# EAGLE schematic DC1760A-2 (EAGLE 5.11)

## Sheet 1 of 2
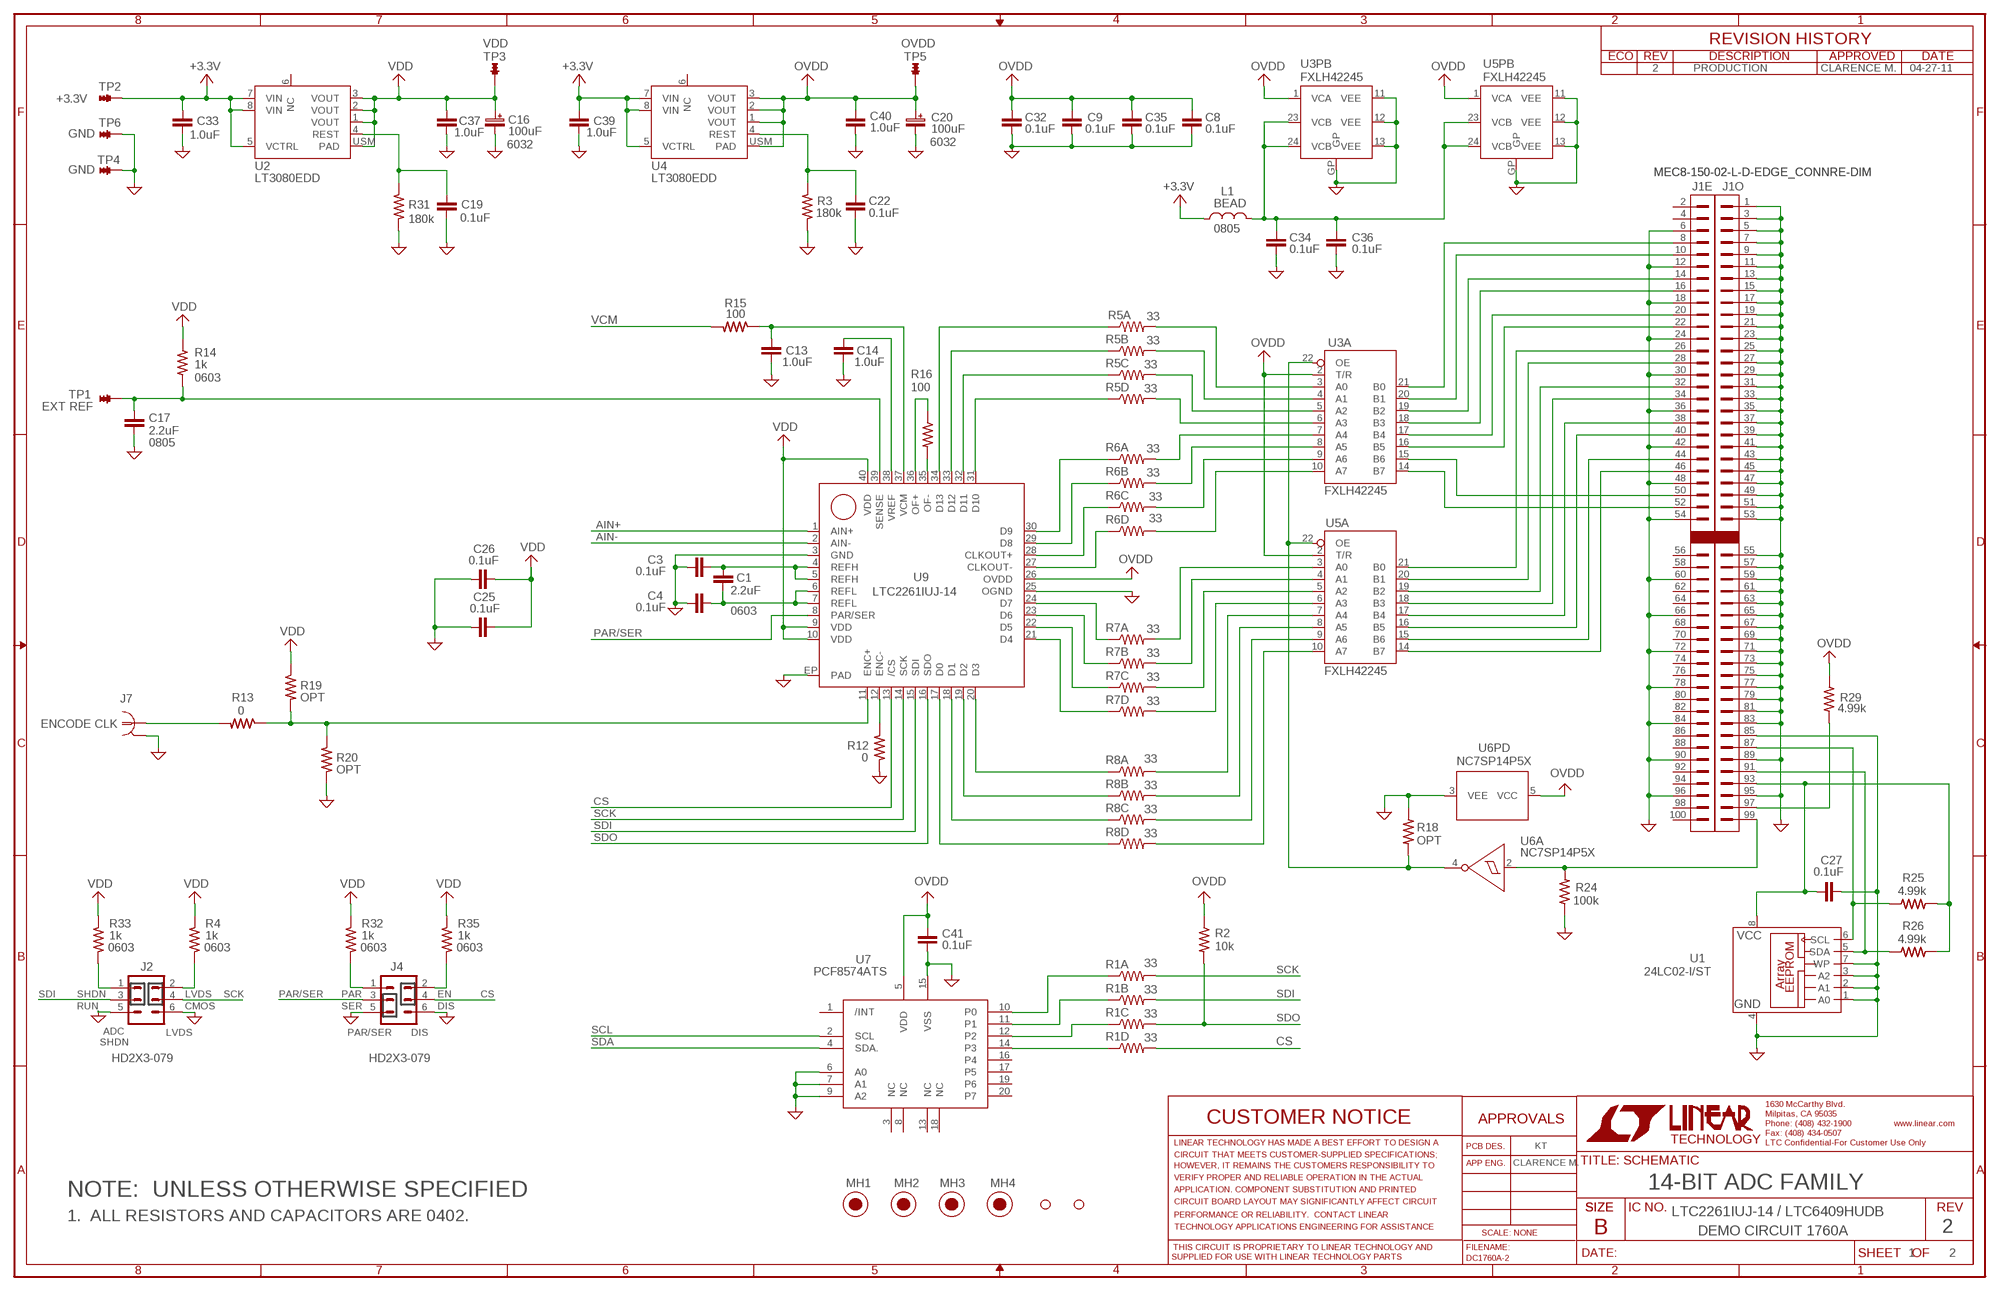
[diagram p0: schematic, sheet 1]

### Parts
C1  2.2uF  CAP-NP-SMT-0603  [0603]
C3  0.1uF  CAP-NP-SMT-0402  [0402]
C4  0.1uF  CAP-NP-SMT-0402  [0402]
C8  0.1uF  CAP-NP-SMT-0402  [0402]
C9  0.1uF  CAP-NP-SMT-0402  [0402]
C13  1.0uF  CAP-NP-SMT-0402  [0402]
C14  1.0uF  CAP-NP-SMT-0402  [0402]
C16  100uF  CAP-POL-TAN-SMT-EIA6032-28  [EIA6032-28(C)]
C17  2.2uF  CAP-NP-SMT-0805  [0805]
C19  0.1uF  CAP-NP-SMT-0402  [0402]
C20  100uF  CAP-POL-TAN-SMT-EIA6032-28  [EIA6032-28(C)]
C22  0.1uF  CAP-NP-SMT-0402  [0402]
C25  0.1uF  CAP-NP-SMT-0402  [0402]
C26  0.1uF  CAP-NP-SMT-0402  [0402]
C27  0.1uF  CAP-NP-SMT-0402  [0402]
C32  0.1uF  CAP-NP-SMT-0402  [0402]
C33  1.0uF  CAP-NP-SMT-0402  [0402]
C34  0.1uF  CAP-NP-SMT-0402  [0402]
C35  0.1uF  CAP-NP-SMT-0402  [0402]
C36  0.1uF  CAP-NP-SMT-0402  [0402]
C37  1.0uF  CAP-NP-SMT-0402  [0402]
C39  1.0uF  CAP-NP-SMT-0402  [0402]
C40  1.0uF  CAP-NP-SMT-0402  [0402]
C41  0.1uF  CAP-NP-SMT-0402  [0402]
J1  MEC8-150-02-L-D-EDGE_CONNRE-DIM  [MEC8-150-02-L-D-EDGE_CONN-NEW-ORIGIN]
J2  HD2X3-079  HDR-3X2-PS  [HD2X3-079]
J4  HD2X3-079  HDR-3X2-PS  [HD2X3-079]
J7  RF_CONNSMA-EDGE-MNT  [SMA-EDGE-MNT]
L1  BEAD  IND-CER-SMT-0805  [R0805]
MH1  MTG-8831-STANDOFF  [MTG-8831]
MH2  MTG-8831-STANDOFF  [MTG-8831]
MH3  MTG-8831-STANDOFF  [MTG-8831]
MH4  MTG-8831-STANDOFF  [MTG-8831]
R1  33  RES_ARRAY_QUAD-33-MNR04  [MNR04-QUAD-RES-ARRAY]
R2  10k  RES-0402  [0402]
R3  180k  RES-0402  [0402]
R4  1k  RES-0603  [0603]
R5  33  RES_ARRAY_QUAD-33-MNR04  [MNR04-QUAD-RES-ARRAY]
R6  33  RES_ARRAY_QUAD-33-MNR04  [MNR04-QUAD-RES-ARRAY]
R7  33  RES_ARRAY_QUAD-33-MNR04  [MNR04-QUAD-RES-ARRAY]
R8  33  RES_ARRAY_QUAD-33-MNR04  [MNR04-QUAD-RES-ARRAY]
R12  0  RES-0402  [0402]
R13  0  RES-0402  [0402]
R14  1k  RES-0603  [0603]
R15  100  RES-0402  [0402]
R16  100  RES-0201  [0201]
R18  OPT  RES-0402  [0402]
R19  OPT  RES-0402  [0402]
R20  OPT  RES-0402  [0402]
R24  100k  RES-0402  [0402]
R25  4.99k  RES-0402  [0402]
R26  4.99k  RES-0402  [0402]
R29  4.99k  RES-0402  [0402]
R31  180k  RES-0402  [0402]
R32  1k  RES-0603  [0603]
R33  1k  RES-0603  [0603]
R35  1k  RES-0603  [0603]
TP1  TURRET-064  [MILLMAX-2308-2]
TP2  TURRET-064  [MILLMAX-2308-2]
TP3  TURRET-064  [MILLMAX-2308-2]
TP4  TURRET-064  [MILLMAX-2308-2]
TP5  TURRET-064  [MILLMAX-2308-2]
TP6  TURRET-064  [MILLMAX-2308-2]
U1  24LC02-I/ST  24LC02ST  [TSSOP8]
U2  LT3080EDD  LT3080  [DFN-8_3X3MM@1]
U3  FXLH42245  [DFN_8X4]
U4  LT3080EDD  LT3080  [DFN-8_3X3MM@1]
U5  FXLH42245  [DFN_8X4]
U6  NC7SP14P5X  NC7SP17P5X  [SC70-5]
U7  PCF8574ATS  PCF8574  [SSOP20]
U9  LTC2261IUJ-14  LTC2261  [TQFN_6X6_40PIN]
X1  TOOLINGHOLE-70MIL  [TOOLINGHOLE]
X2  TOOLINGHOLE-70MIL  [TOOLINGHOLE]

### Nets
+3.3V: C33.2 C39.2 L1.1 TP2.1 U2.5(VCTRL) U2.7(VIN) U2.8(VIN) U4.5(VCTRL) U4.7(VIN) U4.8(VIN)
AIN+: U9.1(AIN+) ; also sheet 2
AIN-: U9.2(AIN-) ; also sheet 2
CS: J4.4 R1.5 U9.13(/CS)
EXTREF: C17.1 R14.1 TP1.1 U9.39(SENSE)
GND: C3.1 C4.1 C8.2 C9.2 C13.2 C14.1 C16.K C17.2 C19.2 C20.K C22.2 C25.1 C26.1 C27.2 C32.2 C33.1 C34.2 C35.2 C36.2 C37.1 C39.1 C40.1 C41.2 J1.1 J1.3 J1.5 J1.6 J1.7 J1.9 J1.11 J1.12 J1.13 J1.15 J1.17 J1.18 J1.19 J1.21 J1.23 J1.24 J1.25 J1.27 J1.29 J1.30 J1.31 J1.33 J1.35 J1.36 J1.37 J1.39 J1.41 J1.42 J1.43 J1.45 J1.47 J1.48 J1.49 J1.51 J1.53 J1.54 J1.55 J1.57 J1.59 J1.60 J1.61 J1.63 J1.65 J1.66 J1.67 J1.69 J1.71 J1.72 J1.73 J1.75 J1.77 J1.78 J1.79 J1.81 J1.83 J1.84 J1.85 J1.89 J1.90 J1.95 J1.96 J2.5 J2.6 J4.5 J4.6 J7.2(GND) R3.2 R12.2 R18.1 R20.2 R24.1 R31.2 TP4.1 TP6.1 U1.1(A0) U1.2(A1) U1.3(A2) U1.4(GND) U1.7(WP) U3.11(PB:VEE) U3.12(PB:VEE) U3.13(PB:VEE) U3.GP(PB:GP) U5.11(PB:VEE) U5.12(PB:VEE) U5.13(PB:VEE) U5.GP(PB:GP) U6.3(PD:VEE) U7.6(A0) U7.7(A1) U7.9(A2) U7.15(VSS) U9.3(GND) U9.25(OGND) U9.EP(PAD) ; also sheet 2
N$1: R1.1 U7.10(P0)
N$2: R13.1 R19.2 R20.1 U9.11(ENC+)
N$3: J1.99 R24.2 U6.2(A:A)
N$4: J7.1 R13.2
N$5: R1.2 U7.11(P1)
N$6: J2.2 R4.1
N$7: C19.1 R31.1 U2.4(REST)
N$8: R1.3 U7.12(P2)
N$10: C22.1 R3.1 U4.4(REST)
N$11: J2.1 R33.1
N$13: R12.1 U9.12(ENC-)
N$16: R1.4 U7.14(P3)
N$25: J4.1 R32.1
N$27: J4.2 R35.1
N$28: C1.1 C3.2 U9.4(REFH) U9.5(REFH)
N$29: C1.2 C4.2 U9.6(REFL) U9.7(REFL)
N$30: R5.1 U9.34(D13)
N$31: R5.2 U9.33(D12)
N$32: R5.3 U9.32(D11)
N$33: C14.2 U9.38(VREF)
N$34: R5.4 U9.31(D10)
N$35: R5.8 U3.3(A:A0)
N$36: R5.7 U3.4(A:A1)
N$37: R5.6 U3.5(A:A2)
N$38: R5.5 U3.6(A:A3)
N$39: R6.1 U9.30(D9)
N$40: R6.8 U3.7(A:A4)
N$41: R6.2 U9.29(D8)
N$42: R6.7 U3.8(A:A5)
N$43: R6.3 U9.28(CLKOUT+)
N$44: R6.4 U9.27(CLKOUT-)
N$45: R6.6 U3.9(A:A6)
N$46: R6.5 U3.10(A:A7)
N$47: R7.1 U9.24(D7)
N$48: R7.2 U9.23(D6)
N$49: R7.3 U9.22(D5)
N$50: R7.4 U9.21(D4)
N$51: R7.8 U5.3(A:A0)
N$52: R7.7 U5.4(A:A1)
N$53: R7.6 U5.5(A:A2)
N$54: R7.5 U5.6(A:A3)
N$55: R8.1 U9.20(D3)
N$56: R8.8 U5.7(A:A4)
N$57: R8.2 U9.19(D2)
N$58: R8.7 U5.8(A:A5)
N$59: R8.3 U9.18(D1)
N$60: R8.6 U5.9(A:A6)
N$63: R8.4 U9.17(D0)
N$64: R8.5 U5.10(A:A7)
N$65: J1.8 U3.21(A:B0)
N$66: J1.10 U3.20(A:B1)
N$67: J1.14 U3.19(A:B2)
N$68: J1.16 U3.18(A:B3)
N$69: J1.20 U3.17(A:B4)
N$70: J1.22 U3.16(A:B5)
N$71: J1.50 U3.15(A:B6)
N$72: J1.52 U3.14(A:B7)
N$73: J1.26 U5.21(A:B0)
N$74: J1.28 U5.20(A:B1)
N$75: J1.32 U5.19(A:B2)
N$76: J1.34 U5.18(A:B3)
N$77: J1.38 U5.17(A:B4)
N$78: J1.40 U5.16(A:B5)
N$79: J1.44 U5.15(A:B6)
N$80: J1.46 U5.14(A:B7)
N$82: C13.1 R15.1 U9.37(VCM)
N$94: C34.1 C36.1 L1.2 U3.23(PB:VCB) U3.24(PB:VCB) U5.23(PB:VCB) U5.24(PB:VCB)
N$96: R16.2 U9.35(OF-)
N$103: R16.1 U9.36(OF+)
OUT-ENABLE: R18.2 U3.22(A:OE) U5.22(A:OE) U6.4(A:Y)
OVDD: C8.1 C9.1 C20.A C32.1 C35.1 C40.2 C41.1 R2.1 R29.2 TP5.1 U3.1(PB:VCA) U3.2(A:T/R) U4.1(VOUT) U4.2(VOUT) U4.3(VOUT) U4.USM(PAD) U5.1(PB:VCA) U5.2(A:T/R) U6.5(PD:VCC) U7.5(VDD) U9.26(OVDD)
PAR/SER: J4.3 U9.8(PAR/SER)
PWR-ON: J1.97 R29.1
SCK: J2.4 R1.8 U9.14(SCK)
SCL: J1.87 R25.1 U1.6(SCL) U7.2(SCL)
SDA: J1.91 R26.1 U1.5(SDA) U7.4(SDA.)
SDI: J2.3 R1.7 U9.15(SDI)
SDO: R1.6 R2.2 U9.16(SDO)
VCM: R15.2 ; also sheet 2
VDD: C16.A C25.2 C26.2 C37.2 R4.2 R14.2 R19.1 R32.2 R33.2 R35.2 TP3.1 U2.1(VOUT) U2.2(VOUT) U2.3(VOUT) U2.USM(PAD) U9.9(VDD) U9.10(VDD) U9.40(VDD)
VROM: C27.1 J1.93 R25.2 R26.2 U1.8(VCC)
Unconnected: J1.2 J1.4 J1.56 J1.58 J1.62 J1.64 J1.68 J1.70 J1.74 J1.76 J1.80 J1.82 J1.86 J1.88 J1.92 J1.94 J1.98 J1.100 MH1.1 MH2.1 MH3.1 MH4.1 U2.6(NC) U4.6(NC) U7.1(/INT) U7.3(NC) U7.8(NC) U7.13(NC) U7.16(P4) U7.17(P5) U7.18(NC) U7.19(P6) U7.20(P7) X1.1 X2.1

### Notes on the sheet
- VDD | OVDD
- 2 | PRODUCTION | CLARENCE M. | 04-27-11
- +3.3V
- GND
- 6032 | 6032
- GND
- 0805
- 0603
- EXT REF
- 0805
- 0603
- ENCODE CLK
- 0603 | 0603 | 0603 | 0603
- SHDN | LVDS | PAR | EN
- RUN | CMOS | SER | DIS
- ADC | LVDS | PAR/SER | DIS
- SHDN
- KT
- CLARENCE M.
- MH1 | MH2 | MH3 | MH4 | 14-BIT ADC FAMILY
- NOTE:  UNLESS OTHERWISE SPECIFIED
- LTC2261IUJ-14 / LTC6409HUDB
- 1.  ALL RESISTORS AND CAPACITORS ARE 0402.
- DEMO CIRCUIT 1760A | 2
- 1 | 2

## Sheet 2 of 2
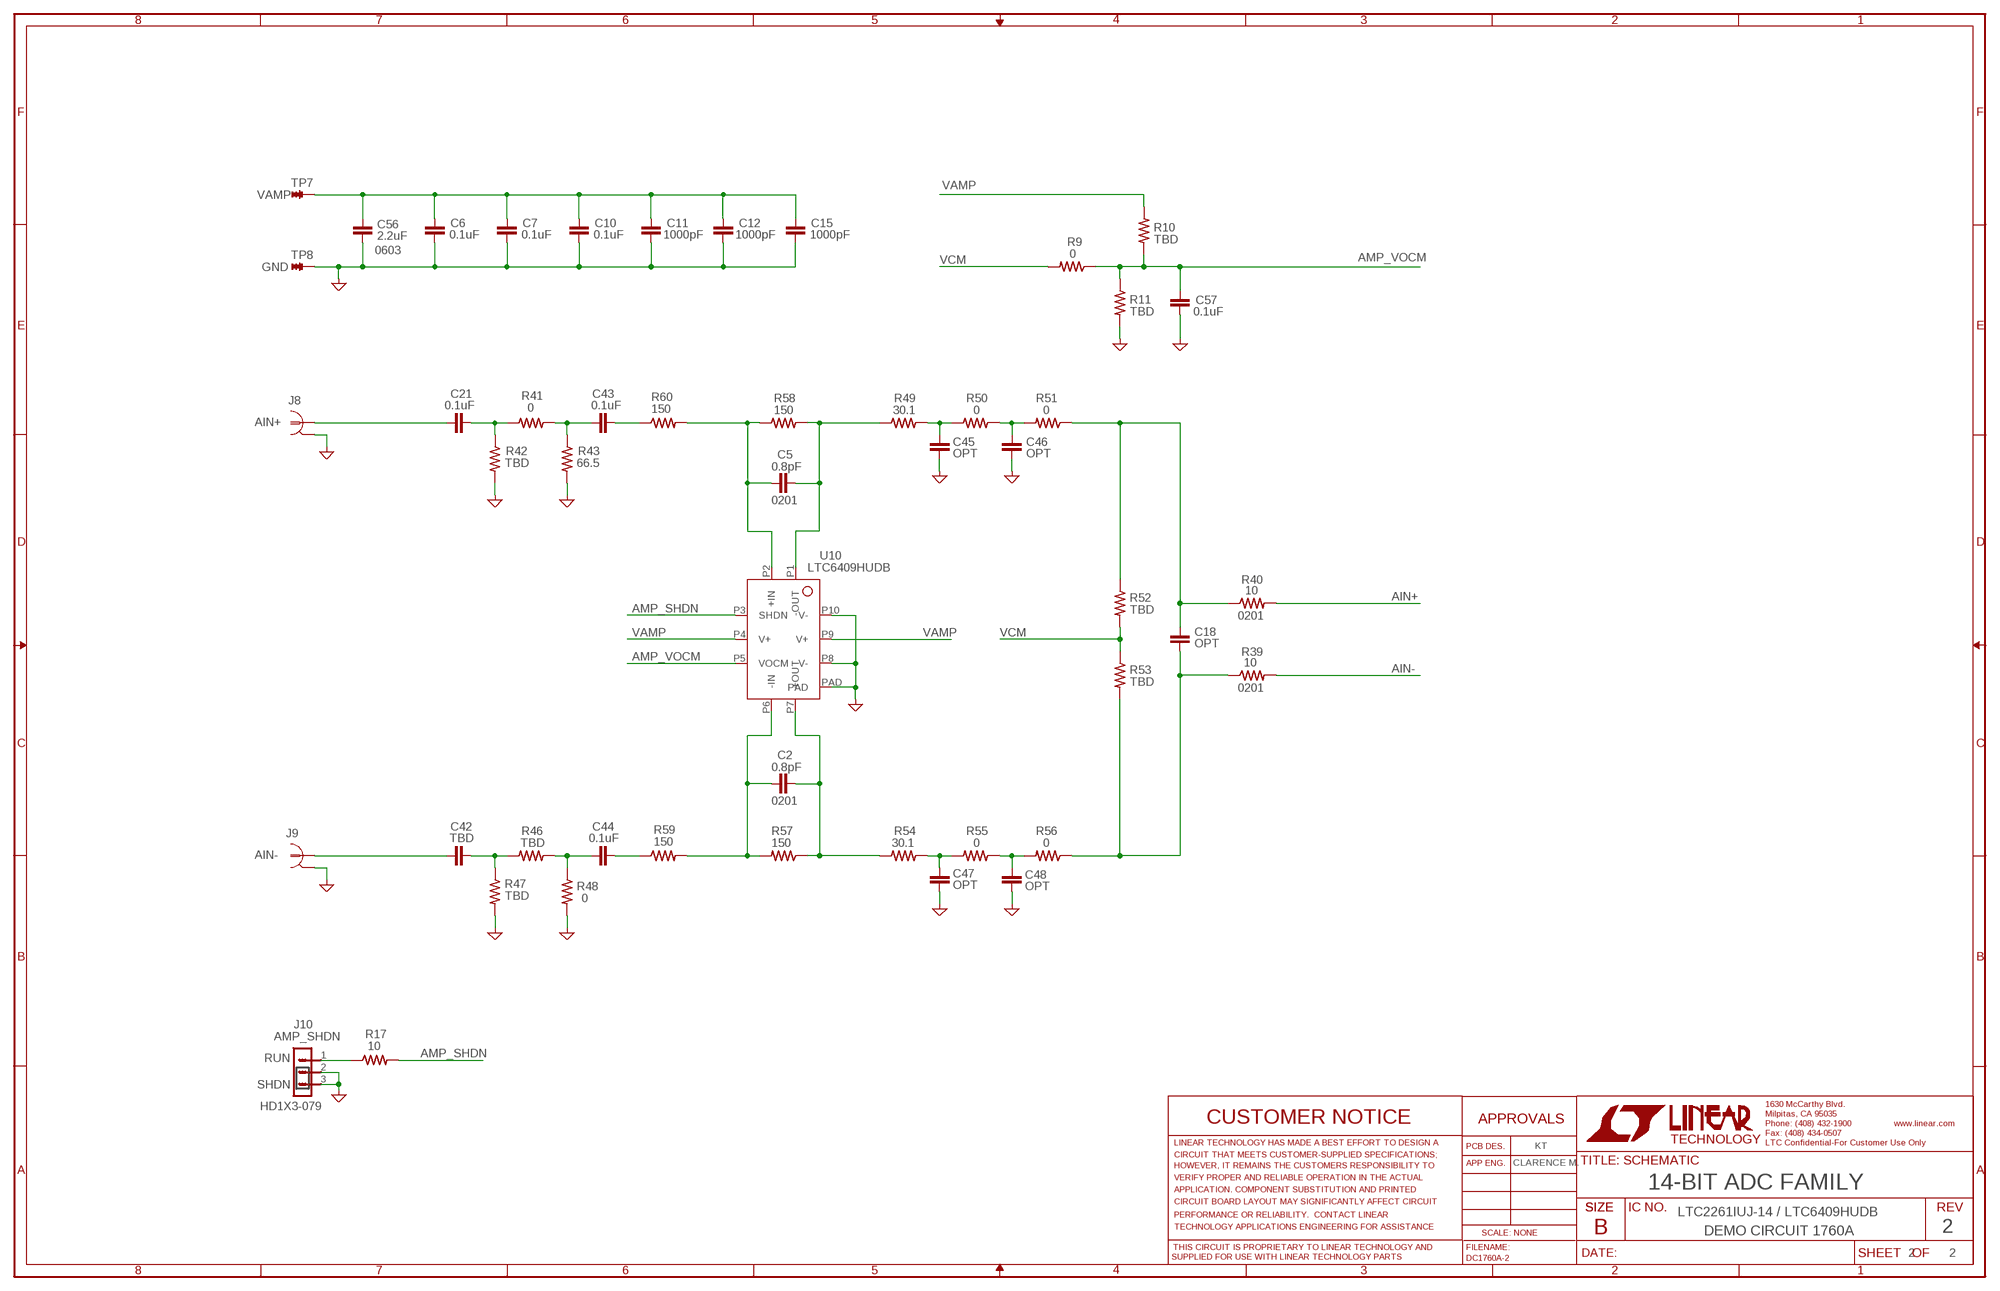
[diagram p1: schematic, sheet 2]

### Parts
C2  0.8pF  CAP-NP-0201  [0201]
C5  0.8pF  CAP-NP-0201  [0201]
C6  0.1uF  CAP-NP-SMT-0402  [0402]
C7  0.1uF  CAP-NP-SMT-0402  [0402]
C10  0.1uF  CAP-NP-SMT-0402  [0402]
C11  1000pF  CAP-NP-SMT-0402  [0402]
C12  1000pF  CAP-NP-SMT-0402  [0402]
C15  1000pF  CAP-NP-SMT-0402  [0402]
C18  OPT  CAP-NP-SMT-0402  [0402]
C21  0.1uF  CAP-NP-SMT-0402  [0402]
C42  TBD  CAP-NP-SMT-0402  [0402]
C43  0.1uF  CAP-NP-SMT-0402  [0402]
C44  0.1uF  CAP-NP-SMT-0402  [0402]
C45  OPT  CAP-NP-SMT-0402  [0402]
C46  OPT  CAP-NP-SMT-0402  [0402]
C47  OPT  CAP-NP-SMT-0402  [0402]
C48  OPT  CAP-NP-SMT-0402  [0402]
C56  2.2uF  CAP-NP-SMT-0603  [0603]
C57  0.1uF  CAP-NP-SMT-0402  [0402]
J8  RF_CONNSMA-EDGE-MNT  [SMA-EDGE-MNT]
J9  RF_CONNSMA-EDGE-MNT  [SMA-EDGE-MNT]
J10  HD1X3-079  JMPR-3X1-PS2MM  [HDR-3X1PS-2MM]
R9  0  RES-0402  [0402]
R10  TBD  RES-0402  [0402]
R11  TBD  RES-0402  [0402]
R17  10  RES-0402  [0402]
R39  10  RES-0201  [0201]
R40  10  RES-0201  [0201]
R41  0  RES-0402  [0402]
R42  TBD  RES-0402  [0402]
R43  66.5  RES-0402  [0402]
R46  TBD  RES-0402  [0402]
R47  TBD  RES-0402  [0402]
R48  0  RES-0402  [0402]
R49  30.1  RES-0402  [0402]
R50  0  RES-0402  [0402]
R51  0  RES-0402  [0402]
R52  TBD  RES-0402  [0402]
R53  TBD  RES-0402  [0402]
R54  30.1  RES-0402  [0402]
R55  0  RES-0402  [0402]
R56  0  RES-0402  [0402]
R57  150  RES-0402  [0402]
R58  150  RES-0402  [0402]
R59  150  RES-0402  [0402]
R60  150  RES-0402  [0402]
TP7  TURRET-064  [MILLMAX-2308-2]
TP8  TURRET-064  [MILLMAX-2308-2]
U10  LTC6409HUDB  LTC6409  [TQFN_3MM_X_2MM]

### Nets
AIN+: R40.2 ; also sheet 1
AIN-: R39.2 ; also sheet 1
AMP_SHDN: R17.2 U10.P3(SHDN)
AMP_VOCM: C57.1 R9.1 R10.2 R11.1 U10.P5(VOCM)
GND: C6.2 C7.2 C10.2 C11.2 C12.2 C15.2 C45.1 C46.1 C47.1 C48.1 C56.1 C57.2 J8.2(GND) J9.2(GND) J10.2 J10.3 R11.2 R42.2 R43.2 R47.2 R48.2 TP8.1 U10.P8(V-) U10.P10(V-) U10.PAD ; also sheet 1
N$9: C21.1 J8.1
N$12: J10.1 R17.1
N$15: C2.2 R54.2 R57.1 U10.P7(+OUT)
N$18: C5.2 R49.2 R58.2 U10.P1(-OUT)
N$26: C18.1 R39.1 R53.2 R56.1
N$92: C21.2 R41.1 R42.1
N$97: C42.1 J9.1
N$98: C42.2 R46.1 R47.1
N$99: C43.1 R41.2 R43.1
N$101: C44.1 R46.2 R48.1
N$102: C2.1 R57.2 R59.2 U10.P6(-IN)
N$104: C5.1 R58.1 R60.2 U10.P2(+IN)
N$106: C45.2 R49.1 R50.2
N$107: C46.2 R50.1 R51.2
N$108: C18.2 R40.1 R51.1 R52.1
N$110: C47.2 R54.1 R55.2
N$111: C48.2 R55.1 R56.2
N$114: C44.2 R59.1
N$115: C43.2 R60.1
VAMP: C6.1 C7.1 C10.1 C11.1 C12.1 C15.1 C56.2 R10.1 TP7.1 U10.P4(V+) U10.P9(V+)
VCM: R9.2 R52.2 R53.1 ; also sheet 1

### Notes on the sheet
- 0603
- GND
- AIN+
- 0201
- 0201
- 0201
- 0201
- AIN-
- AMP_SHDN
- RUN
- SHDN
- KT
- CLARENCE M.
- 14-BIT ADC FAMILY
- LTC2261IUJ-14 / LTC6409HUDB
- DEMO CIRCUIT 1760A | 2
- 2 | 2

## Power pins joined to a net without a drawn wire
GND: J7.3(GND) J7.4(GND) J7.5(GND) J8.3(GND) J8.4(GND) J8.5(GND) J9.3(GND) J9.4(GND) J9.5(GND)

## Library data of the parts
C1 C3 C4 C6-C15 C17-C19 C21 C22 C25-C27 C32-C37 C39-C48 C56 C57 = LTDB_Passives:CAP-NP-SMT-: Capacitor; Non-polar; SMT
C2 C5 = EagleLib:CAP-NP
C16 C20 = LTDB_Passives:CAP-POL-TAN-SMT-: EIA STD SMT TANTALUM CAPACITORS
J1 = LTDB_Connectors:MEC8-150-02-L-D-EDGE_CONN
J2 J4 = LTDB_Connectors:HDR-3X2-PS: Header 3x2 Pin, Straight
J7-J9 = LTDB_Connectors:RF_CONN: BNC CONNECTOR M/A COM www.macom.com distributor Farnell 149-452
J10 = LTDB_Connectors:JMPR-3X1-PS: Jumper,3pin, point connections
L1 = LTDB_Passives:IND-CER-SMT-: Inductor,Ceramic,SMT
MH1-MH4 = EagleLib:MTG-8831
R1 R5-R8 = LTDB_Passives:RES_ARRAY_QUAD-*-?: Reistor Array, Quad, SMT, 25x50 mils, Rohm
R2-R4 R9-R20 R24-R26 R29 R31-R33 R35 R39-R43 R46-R60 = LTDB_Passives:RES-: Resistor; GP
TP1-TP8 = LTDB_Connectors:TURRET: Turret
U1 = LTDB_ICs:24*?: I2C SEEP Memory
U2 U4 = LTDB_Linear_Parts:LT3080
U3 U5 = LTDB_ICs:FXLH42245: Level Translater, Bidirectional, Octal
U6 = LTDB_ICs:NC7SP17?
U7 = LTDB_ICs:PCF8574
U9 = LTDB_Linear_Parts:LTC2261
U10 = LTDB_Linear_Parts:LTC6409
X1 X2 = EagleLib:TOOLINGHOLE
